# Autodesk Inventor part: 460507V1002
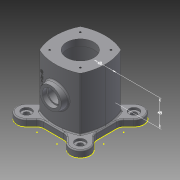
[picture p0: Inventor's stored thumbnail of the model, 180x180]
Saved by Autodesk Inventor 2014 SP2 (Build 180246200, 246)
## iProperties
Created: 2016-05
Part Number: 460507V1002
Material: Generic
Document SubType Name: Modeling
Designer: 달님반
Density: 1 g/cm^3
Appearance: Default
Author: 달님반
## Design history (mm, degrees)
sketch "스케치1"
  geometry: L1 (46, 0)-(46, -0.095); L2 (46, -46)-(-46, -46); L3 (-0.047, -0.047)-(66.486, -66.58); L4 (66.486, -66.58)-(-51.682, 51.587); L5 (-46, -46)-(46, 46); L6 (-46, -26.455)-(-46, 0); L7 (-46, 45.905)-(-46, 46); L8 (-0.095, 46)-(0, 46); A1 r 53 centre (-0.047, -0.047) between (-46, -26.455) and (-37.524, -37.524); A2 r 87.09 centre (41.09, -0.047) between (-37.524, 37.429) and (-37.524, -37.524); A3 r 86.222 centre (-0.047, -40.222) between (37.429, 37.429) and (-37.524, 37.429); A4 r 86.221 centre (-40.221, -0.047) between (37.429, -37.524) and (37.429, 37.429); A5 r 87.089 centre (-0.047, 41.089) between (-37.524, -37.524) and (37.429, -37.524); 1 further point
  constraints: 16 end point, 15 point on circle, 5 centre point, 5 point on line, 3 parallel, 2 perpendicular, 1 collinear, 1 horizontal, 1 horizontal alignment
  dimensions: "d1" = 106 diameter of A1; "d3" = 92 distance of L5.end L2.start; "d4" = 92 distance of L2.start L2.end
extrude "돌출1" new body sketch "스케치1" distance "d5" = 110; taper "d6" = 0 deg
sketch "스케치2" dims "d7" = 140
  geometry: L1 (-46, -0.095)-(-46, 0) reference; L2 (0, 46)-(0.095, 46) reference; L3 (0, 0)-(37.524, -37.524); L4 (59.177, -59.177)-(34.385, -34.385); L5 (62.225, -36.77)-(52.661, -27.205); L6 (36.77, -62.225)-(27.205, -52.661); L7 (-49, 49)-(49, 49); L8 (49, 49)-(49, -49); L9 (49, -49)-(-49, -49); L10 (-49, -49)-(-49, 49); C1 r 18 at (49.497, 49.497); C2 r 18 at (-49.497, 49.497); C3 r 18 at (-49.497, -49.497); A1 r 86.221 centre (40.221, -0.047) between (-37.429, 37.429) and (-46, 0) reference; A2 r 86.221 centre (40.221, -0.047) between (-46, -0.095) and (-37.429, -37.524) reference; A3 r 87.089 centre (0.047, 41.089) between (-37.429, -37.524) and (37.524, -37.524) reference; A4 r 87.09 centre (-41.09, -0.047) between (37.524, -37.524) and (37.524, 37.429) reference; A5 r 86.222 centre (0.047, -40.222) between (37.524, 37.429) and (0.095, 46) reference; A6 r 86.222 centre (0.047, -40.222) between (0, 46) and (-37.429, 37.429) reference; A7 r 18 centre (49.497, -49.497) between (62.225, -36.77) and (36.77, -62.225); A8 r 12.5 centre (61.5, -18.366) between (49, -18.366) and (52.661, -27.205); A9 r 12.5 centre (18.366, -61.5) between (27.205, -52.661) and (18.366, -49); 2 further points
  constraints: 16 end point, 6 centre point, 6 point on circle, 5 point on line, 4 parallel, 4 tangent, 1 coincident, 1 horizontal, 1 horizontal alignment, 1 midpoint, 1 perpendicular, 13 other
  dimensions: "d8" = 36 diameter of A7; "d11" = 360 deg dimension on L3.start A7.centre (derived); "d13" = 36 distance between parallel lines of L6 L5; "d14" = 98 distance of L7.start L7.end; "d15" = 98 distance of L7.end L8.end; "d16" = 25 diameter of A8; "d17" = 25 diameter of A9
extrude "돌출2" join sketch "스케치2" distance "d18" = 12; taper "d19" = 0 deg
sketch "스케치4"
  geometry: C1 r 25 at (0, 0); 1 further point
  constraints: 1 centre point, 1 coincident
  dimensions: "d20" = 50 diameter of C1
extrude "돌출3" cut sketch "스케치4" stored distance "d21" = 12; taper "d22" = 0 deg
sketch "스케치5"
  geometry: C1 r 35 at (0, 0); 1 further point
  constraints: 1 centre point, 1 coincident
  dimensions: "d24" = 70 diameter of C1
extrude "돌출4" cut sketch "스케치5" distance "d25" = 12; taper "d26" = 0 deg
sketch "스케치6"
  geometry: C1 r 35 at (0, 0); 1 further point
  constraints: 1 centre point, 1 coincident
  dimensions: "d27" = 70 diameter of C1
extrude "돌출5" cut sketch "스케치6" distance "d28" = 86; taper "d29" = 0 deg
sketch "스케치7"
  geometry: A1 r 18 centre (49.497, -49.497) between (36.77, -62.225) and (62.225, -36.77) reference; A2 r 18 centre (49.497, 49.497) between (62.225, 36.77) and (36.77, 62.225) reference; A3 r 18 centre (-49.497, 49.497) between (-36.77, 62.225) and (-62.225, 36.77) reference; A4 r 18 centre (-49.497, -49.497) between (-62.225, -36.77) and (-36.77, -62.225) reference; 1 further point
hole "구멍1" sketch "스케치7" at (-49.497, 49.497), (49.497, 49.497), (49.497, -49.497), (-49.497, -49.497) diameter "d33" = 10; stored, may be unused: countersink angle "d37" = 90 deg, drill point angle "d39" = 118 deg; dims "d34" = 6, "d35" = 18, "d36" = 4, "d38" = 8
node "작업 평면1"
sketch "스케치8"
  geometry: L1 (-18.414, 12)-(18.319, 12) reference; C1 r 20 at (-0.047, 61); 1 further point
  constraints: 1 centre point
  dimensions: "d40" = 40 diameter of C1; "d41" = 49 distance from line of C1.centre L1
node "작업 평면2"
fillet "모깎기1" dims "d51" = 2
fillet "모깎기2" dims "d52" = 2
node "작업 평면3"
sketch "스케치12"
  geometry: L1 (-34.953, 12)-(35.047, 12) reference; C1 r 20 at (0.047, 61); 1 further point
  constraints: 1 centre point
  dimensions: "d54" = 40 diameter of C1; "d55" = 49 distance from line of C1.centre L1
node "작업 평면4"
node "작업 평면5"
sketch "스케치13"
  geometry: C1 r 20 at (0, 61) reference; 1 further point
extrude "돌출9" join sketch "스케치13" stored distance "d58" = 20; taper "d59" = 10 deg
sketch "스케치14"
  geometry: C1 r 20 at (0, 0) reference; C2 r 15 at (0, 0); 1 further point
  constraints: 1 centre point, 1 coincident
  dimensions: "d60" = 30 diameter of C2
extrude "돌출10" cut sketch "스케치14" distance "d61" = 8; taper "d62" = 0 deg
sketch "스케치15"
  geometry: C1 r 15 at (0, 0) reference; C2 r 12.5 at (0, 0); 1 further point
  constraints: 1 centre point, 1 coincident
  dimensions: "d63" = 25 diameter of C2
extrude "돌출11" cut sketch "스케치15" distance "d64" = 20; taper "d65" = 0 deg
fillet "모깎기4" dims "d66" = 3
fillet "모깎기5" dims "d67" = 3
sketch "스케치16"
  geometry: C1 r 25 at (0, 0) reference; C2 r 25 at (0, 0)
  constraints: 1 centre point, 1 coincident, 1 concentric
extrude "돌출12" cut sketch "스케치16" stored distance "d68" = 20; taper "d69" = 0 deg
fillet "모깎기6" dims "d70" = 3
node "작업 평면7"
  node "작업 평면6"
sketch "스케치18"
  geometry: L1 (42.481, 110)-(-29.373, 110) reference; 2 further points
  constraints: 1 other
  dimensions: "d73" = 49 distance from line of point (-22.312, 61) L1
feature "엠보싱1" sketch "스케치18" dims "d74" = 0.5, "d75" = 0
sketch "스케치19" dims "d76" = 80
  geometry: L1 (0, 0)-(-35.265, 35.181); C1 r 25 at (0, 0) reference; A1 r 3 centre (-35.265, 35.181) between (-36.535, 37.899) and (-37.989, 36.438) reference; 1 further point
  constraints: 2 end point, 1 coincident, 1 point on line, 3 other
hole "구멍2" sketch "스케치19" at (-28.318, 28.251) diameter "d77" = 3.242; stored, may be unused: countersink angle "d81" = 90 deg, drill point angle "d83" = 118 deg; dims "d78" = 7, "d79" = 18, "d80" = 4, "d82" = 10
sketch "스케치20"
  geometry: L1 (27.205, -52.661)-(36.77, -62.225) reference; L2 (62.225, -36.77)-(52.661, -27.205) reference; L3 (49, -18.366)-(49, 18.366) reference; L4 (52.661, 27.205)-(62.225, 36.77) reference; L5 (36.77, 62.225)-(27.205, 52.661) reference; L6 (18.366, 49)-(-18.366, 49) reference; L7 (-27.205, 52.661)-(-36.77, 62.225) reference; L8 (-62.225, 36.77)-(-52.661, 27.205) reference; L9 (-49, 18.366)-(-49, -18.366) reference; L10 (-52.661, -27.205)-(-62.225, -36.77) reference; L11 (-36.77, -62.225)-(-27.205, -52.661) reference; L12 (-18.366, -49)-(18.366, -49) reference; C1 r 25 at (0, 0) reference; C2 r 5 at (-49.497, -49.497) reference; C3 r 5 at (49.497, 49.497) reference; C4 r 5 at (-49.497, 49.497) reference; C5 r 5 at (49.497, -49.497) reference; A1 r 12.5 centre (18.366, -61.5) between (27.205, -52.661) and (18.366, -49) reference; A2 r 18 centre (49.497, -49.497) between (36.77, -62.225) and (62.225, -36.77) reference; A3 r 12.5 centre (61.5, -18.366) between (49, -18.366) and (52.661, -27.205) reference; A4 r 12.5 centre (61.5, 18.366) between (52.661, 27.205) and (49, 18.366) reference; A5 r 18 centre (49.497, 49.497) between (62.225, 36.77) and (36.77, 62.225) reference; A6 r 12.5 centre (18.366, 61.5) between (18.366, 49) and (27.205, 52.661) reference; A7 r 12.5 centre (-18.366, 61.5) between (-27.205, 52.661) and (-18.366, 49) reference; A8 r 18 centre (-49.497, 49.497) between (-36.77, 62.225) and (-62.225, 36.77) reference; A9 r 12.5 centre (-61.5, 18.366) between (-49, 18.366) and (-52.661, 27.205) reference; A10 r 12.5 centre (-61.5, -18.366) between (-52.661, -27.205) and (-49, -18.366) reference; A11 r 18 centre (-49.497, -49.497) between (-62.225, -36.77) and (-36.77, -62.225) reference; A12 r 12.5 centre (-18.366, -61.5) between (-18.366, -49) and (-27.205, -52.661) reference
node "작업 평면8"
node "솔리드1"
pattern_circular "원형 패턴1" dims angle "d31" = 360 deg
pattern_circular "원형 패턴2" dims angle "d85" = 360 deg
mirror "대칭1"
other parameters: "d42" = 55, "d56" = 55, "d57" = -55, "d71" = -10 deg, "d72" = -65.75
